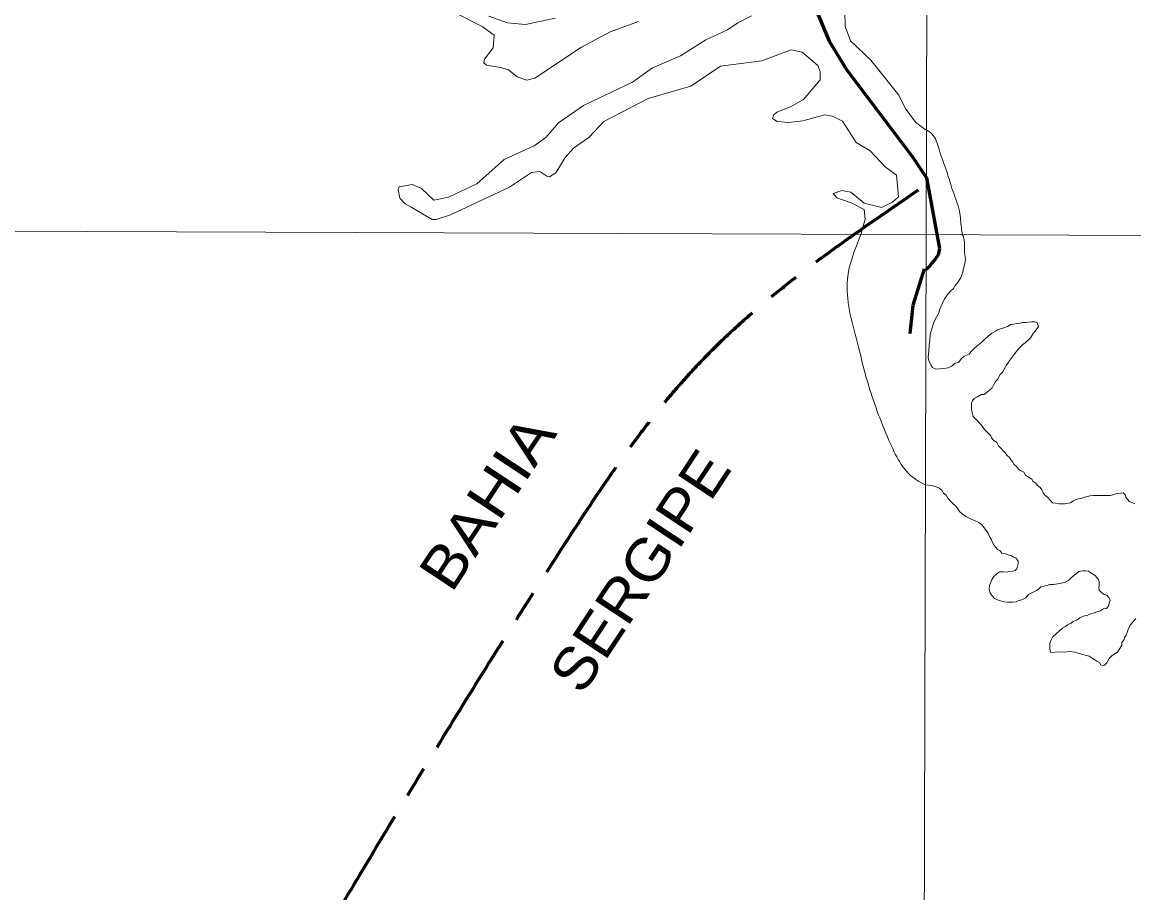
# Model space of a CAD drawing. Extents: x -1643653 to 4543381, y 1624270 to 13878484.
# Drawn here: x 601111 to 611751, y 8943403 to 8951740 of the extents above; entities that cross this region are included whole.
import ezdxf
from ezdxf.enums import TextEntityAlignment as Align

# ---------------------------------------------------------------- set-up
doc = ezdxf.new("R2010")
doc.units = 0
doc.header["$LTSCALE"] = 200
doc.linetypes.add('LONG_DASH_SHORT_DASH', pattern=[9.9, 6, -1.2, 1.5, -1.2])
for name, color, linetype, lineweight in [('1', 7, 'Continuous', 13), ('23', 7, 'Continuous', 13), ('25', 7, 'Continuous', 13), ('60', 7, 'Continuous', 13), ('7', 7, 'LONG_DASH_SHORT_DASH', 60)]:
    doc.layers.add(name, color=color, linetype=linetype, lineweight=lineweight)
doc.layers.add('42', color=7, linetype='Continuous')

msp = doc.modelspace()

# ---------------------------------------------------------------- linework, layer by layer
at = {"layer": '1'}
msp.add_line((565315.3, 8949866.8), (791497.7, 8949052.2), dxfattribs=at)
msp.add_lwpolyline([(609971.9, 9023551.8), (609764.7, 8949706.7), (609734.2, 8939404.4)], dxfattribs=at)
at = {"layer": '23'}
for points in [[(609755.4, 8950712.2), (609661.1, 8950783.5), (609561, 8950917.9), (609502.2, 8951042.1), (609232.8, 8951376.9), (609037.8, 8951563.3), (608987.2, 8951699.7), (608983.5, 8951846.5)], [(609755.4, 8950712.2), (609661.1, 8950783.5), (609561, 8950917.9), (609502.2, 8951042.1), (609232.8, 8951376.9), (609037.8, 8951563.3), (608987.2, 8951699.7), (608983.5, 8951846.5)], [(609792.6, 8948650.3), (609799.1, 8948692.7), (609802.3, 8948751.2), (609825.2, 8948822.9), (609838.2, 8948868.4), (609861, 8948914), (609887.1, 8948962.8), (609893.6, 8948992.1), (609916.4, 8949044.2), (609935.9, 8949083.3), (609968.5, 8949132.1), (610001.1, 8949167.9), (610023.9, 8949190.7), (610040.2, 8949220), (610069.5, 8949252.6), (610095.5, 8949294.9), (610115.1, 8949347), (610121.6, 8949382.8), (610134.6, 8949428.4), (610141.1, 8949473.9), (610130.7, 8949532.9), (610130.9, 8949558), (610131.1, 8949578), (610131.3, 8949608.1), (610129, 8949638.1), (610124.3, 8949673.2), (610117, 8949693.3), (610108.9, 8949704.2)], [(609792.6, 8948650.3), (609799.1, 8948692.7), (609802.3, 8948751.2), (609825.2, 8948822.9), (609838.2, 8948868.4), (609861, 8948914), (609887.1, 8948962.8), (609893.6, 8948992.1), (609916.4, 8949044.2), (609935.9, 8949083.3), (609968.5, 8949132.1), (610001.1, 8949167.9), (610023.9, 8949190.7), (610040.2, 8949220), (610069.5, 8949252.6), (610095.5, 8949294.9), (610115.1, 8949347), (610121.6, 8949382.8), (610134.6, 8949428.4), (610141.1, 8949473.9), (610130.7, 8949532.9), (610130.9, 8949558), (610131.1, 8949578), (610131.3, 8949608.1), (610129, 8949638.1), (610124.3, 8949673.2), (610117, 8949693.3), (610108.9, 8949704.2)], [(610788.6, 8947343.2), (610773.7, 8947363.3), (610741.4, 8947383.6), (610714, 8947401.3), (610696.7, 8947431.4), (610669.3, 8947444.1), (610646.9, 8947459.3), (610629.6, 8947486.9), (610607.2, 8947504.6), (610592.4, 8947527.2), (610577.6, 8947547.4), (610560.2, 8947570), (610537.9, 8947590.2), (610515.6, 8947617.9), (610498.2, 8947638), (610480.8, 8947658.2), (610456, 8947683.4), (610438.8, 8947716), (610408.9, 8947736.2), (610389.1, 8947758.9), (610381.7, 8947779), (610361.9, 8947799.2), (610342, 8947821.8), (610319.7, 8947842), (610299.9, 8947872.2), (610282.5, 8947892.3), (610265.2, 8947912.5), (610232.9, 8947945.2), (610213.1, 8947965.4), (610205.8, 8947990.5), (610198.6, 8948030.6), (610196.3, 8948068.1), (610196.5, 8948090.7), (610206.7, 8948113.1), (610224.4, 8948135.5), (610254.5, 8948152.9), (610292.2, 8948175.1), (610319.7, 8948175), (610342.4, 8948194.8), (610367.5, 8948214.7), (610395.2, 8948239.6), (610407.9, 8948264.5), (610425.7, 8948299.4), (610450.9, 8948321.8), (610458.6, 8948344.3), (610471.2, 8948366.7), (610493.9, 8948389.1), (610533.4, 8948456.2), (610564.5, 8948504.9), (610611, 8948567), (610646.5, 8948613.2), (610686.8, 8948650.5), (610711.9, 8948670.4), (610749.7, 8948705.2), (610767.4, 8948727.6), (610787.7, 8948760), (610807.8, 8948782.4), (610838.2, 8948827.3), (610825.9, 8948859.9), (610803.5, 8948870.1), (610771, 8948870.3), (610741, 8948868), (610720.9, 8948865.6), (610683.4, 8948863.3), (610663.3, 8948858.5), (610630.8, 8948853.7), (610600.7, 8948848.9), (610573.2, 8948846.6), (610540.6, 8948826.7), (610505.4, 8948814.5), (610475.3, 8948802.1), (610447.8, 8948794.8), (610427.6, 8948779.9), (610392.5, 8948762.6), (610372.4, 8948747.7), (610330.1, 8948712.2), (610330.1, 8948712.2), (610297.5, 8948676.4), (610297.5, 8948676.4), (610248.6, 8948637.3), (610219.3, 8948611.3), (610219.3, 8948611.3), (610193.3, 8948585.2), (610173.7, 8948562.4), (610128.1, 8948542.9), (610102.1, 8948520.1), (610076, 8948484.3), (610033.6, 8948471.3), (610010.8, 8948448.5), (609975, 8948429), (609932.7, 8948422.5), (609892.2, 8948420.5), (609854.5, 8948416), (609854.5, 8948416), (609825.2, 8948432.2), (609808.9, 8948458.3), (609808.9, 8948458.3), (609789.3, 8948500.6), (609782.8, 8948533.1), (609789.3, 8948588.5), (609792.6, 8948650.3)], [(610788.6, 8947343.2), (610773.7, 8947363.3), (610741.4, 8947383.6), (610714, 8947401.3), (610696.7, 8947431.4), (610669.3, 8947444.1), (610646.9, 8947459.3), (610629.6, 8947486.9), (610607.2, 8947504.6), (610592.4, 8947527.2), (610577.6, 8947547.4), (610560.2, 8947570), (610537.9, 8947590.2), (610515.6, 8947617.9), (610498.2, 8947638), (610480.8, 8947658.2), (610456, 8947683.4), (610438.8, 8947716), (610408.9, 8947736.2), (610389.1, 8947758.9), (610381.7, 8947779), (610361.9, 8947799.2), (610342, 8947821.8), (610319.7, 8947842), (610299.9, 8947872.2), (610282.5, 8947892.3), (610265.2, 8947912.5), (610232.9, 8947945.2), (610213.1, 8947965.4), (610205.8, 8947990.5), (610198.6, 8948030.6), (610196.3, 8948068.1), (610196.5, 8948090.7), (610206.7, 8948113.1), (610224.4, 8948135.5), (610254.5, 8948152.9), (610292.2, 8948175.1), (610319.7, 8948175), (610342.4, 8948194.8), (610367.5, 8948214.7), (610395.2, 8948239.6), (610407.9, 8948264.5), (610425.7, 8948299.4), (610450.9, 8948321.8), (610458.6, 8948344.3), (610471.2, 8948366.7), (610493.9, 8948389.1), (610533.4, 8948456.2), (610564.5, 8948504.9), (610611, 8948567), (610646.5, 8948613.2), (610686.8, 8948650.5), (610711.9, 8948670.4), (610749.7, 8948705.2), (610767.4, 8948727.6), (610787.7, 8948760), (610807.8, 8948782.4), (610838.2, 8948827.3), (610825.9, 8948859.9), (610803.5, 8948870.1), (610771, 8948870.3), (610741, 8948868), (610720.9, 8948865.6), (610683.4, 8948863.3), (610663.3, 8948858.5), (610630.8, 8948853.7), (610600.7, 8948848.9), (610573.2, 8948846.6), (610540.6, 8948826.7), (610505.4, 8948814.5), (610475.3, 8948802.1), (610447.8, 8948794.8), (610427.6, 8948779.9), (610392.5, 8948762.6), (610372.4, 8948747.7), (610330.1, 8948712.2), (610330.1, 8948712.2), (610297.5, 8948676.4), (610297.5, 8948676.4), (610248.6, 8948637.3), (610219.3, 8948611.3), (610219.3, 8948611.3), (610193.3, 8948585.2), (610173.7, 8948562.4), (610128.1, 8948542.9), (610102.1, 8948520.1), (610076, 8948484.3), (610033.6, 8948471.3), (610010.8, 8948448.5), (609975, 8948429), (609932.7, 8948422.5), (609892.2, 8948420.5), (609854.5, 8948416), (609854.5, 8948416), (609825.2, 8948432.2), (609808.9, 8948458.3), (609808.9, 8948458.3), (609789.3, 8948500.6), (609782.8, 8948533.1), (609789.3, 8948588.5), (609792.6, 8948650.3)], [(611759.9, 8947129), (611732.5, 8947141.7), (611705, 8947149.4), (611695.2, 8947169.4), (611675.3, 8947189.6), (611670.5, 8947209.7), (611650.6, 8947232.3), (611630.6, 8947230), (611598.1, 8947227.7), (611578, 8947222.8), (611558, 8947217.9), (611527.9, 8947208.1), (611507.9, 8947208.2), (611475.4, 8947208.5), (611445.4, 8947208.7), (611422.8, 8947208.8), (611400.3, 8947209), (611380.3, 8947209.1), (611357.8, 8947206.7), (611330.3, 8947204.4), (611310.2, 8947199.5), (611280.2, 8947192.2), (611252.6, 8947182.4), (611222.5, 8947175.1), (611199.9, 8947167.7), (611167.3, 8947152.9), (611144.7, 8947138.1), (611109.6, 8947130.8), (611089.6, 8947128.4), (611057.1, 8947128.6), (611037.1, 8947128.8), (611002.1, 8947134), (610972.1, 8947136.7), (610954.8, 8947159.3), (610925, 8947192.1), (610900.1, 8947212.3), (610882.8, 8947232.4), (610870.5, 8947262.5), (610855.7, 8947285.2), (610825.8, 8947305.4), (610813.5, 8947325.5), (610788.6, 8947343.2)], [(611759.9, 8947129), (611732.5, 8947141.7), (611705, 8947149.4), (611695.2, 8947169.4), (611675.3, 8947189.6), (611670.5, 8947209.7), (611650.6, 8947232.3), (611630.6, 8947230), (611598.1, 8947227.7), (611578, 8947222.8), (611558, 8947217.9), (611527.9, 8947208.1), (611507.9, 8947208.2), (611475.4, 8947208.5), (611445.4, 8947208.7), (611422.8, 8947208.8), (611400.3, 8947209), (611380.3, 8947209.1), (611357.8, 8947206.7), (611330.3, 8947204.4), (611310.2, 8947199.5), (611280.2, 8947192.2), (611252.6, 8947182.4), (611222.5, 8947175.1), (611199.9, 8947167.7), (611167.3, 8947152.9), (611144.7, 8947138.1), (611109.6, 8947130.8), (611089.6, 8947128.4), (611057.1, 8947128.6), (611037.1, 8947128.8), (611002.1, 8947134), (610972.1, 8947136.7), (610954.8, 8947159.3), (610925, 8947192.1), (610900.1, 8947212.3), (610882.8, 8947232.4), (610870.5, 8947262.5), (610855.7, 8947285.2), (610825.8, 8947305.4), (610813.5, 8947325.5), (610788.6, 8947343.2)]]:
    msp.add_lwpolyline(points, dxfattribs=at)
msp.add_spline([(610108.9, 8949704.2), (610092.8, 8949844.8), (610081.3, 8949930.9), (610018.2, 8950125.9), (609960.9, 8950309.5), (609886.3, 8950521.8), (609817.5, 8950670.9), (609755.4, 8950712.2)], degree=3, dxfattribs=at)
msp.add_spline([(610108.9, 8949704.2), (610092.8, 8949844.8), (610081.3, 8949930.9), (610018.2, 8950125.9), (609960.9, 8950309.5), (609886.3, 8950521.8), (609817.5, 8950670.9), (609755.4, 8950712.2)], degree=3, dxfattribs=at)
at = {"layer": '25'}
for points in [[(609755.4, 8950712.2), (609661.1, 8950783.5), (609561, 8950917.9), (609502.2, 8951042.1), (609232.8, 8951376.9), (609037.8, 8951563.3), (608987.2, 8951699.7), (608983.5, 8951846.5)], [(608090.2, 8951799.8), (607960.9, 8951735.6), (607862.5, 8951666.2), (607653, 8951570.5), (607410.8, 8951418.3), (607144.4, 8951302.6), (606950.8, 8951166.6), (606482.1, 8950942.3), (606242.9, 8950775.2), (606123, 8950635.5), (606012.1, 8950556.7), (605725, 8950424.5), (605463.8, 8950193.5), (605190.6, 8950065.5), (605051.5, 8950037.1), (604931.9, 8950147.3), (604842.4, 8950186), (604720.3, 8950162.6), (604710.1, 8950138.4)], [(605267.2, 8951822), (605514.5, 8951699.4), (605627.5, 8951614.5), (605620, 8951495.8), (605536.3, 8951386.5), (605528.7, 8951351.7), (605555.2, 8951329.8), (605690.4, 8951305.3), (605763.9, 8951283), (605848.8, 8951216.1), (605942.1, 8951185.6), (606018, 8951204.4), (606463.2, 8951500.4), (606738.6, 8951647.1), (607011.1, 8951745.5)], [(606213.2, 8951778.7), (605929, 8951719.6), (605757, 8951735), (605578.7, 8951796.6)], [(604710.1, 8950138.4), (604726.6, 8950056.6), (604775, 8950000.1), (604833.2, 8949967.4), (605034.8, 8949852), (605074.3, 8949852.1), (605210.6, 8949895.6), (605776.5, 8950159.4), (605984.7, 8950300.3), (606066, 8950310.7), (606133.6, 8950266.2), (606157.8, 8950260.8), (606219.7, 8950297.6), (606309.2, 8950444.5), (606386.8, 8950535.4), (606539, 8950640.6), (606679, 8950789), (607103.1, 8951009.8), (607511.4, 8951127.6), (607793.4, 8951318.1), (608189.8, 8951370), (608470.1, 8951476.1), (608576.2, 8951452.3), (608726.2, 8951326.4), (608749.8, 8951266.5), (608747.2, 8951186.9), (608590.8, 8950999.1), (608464.4, 8950928.1), (608333.9, 8950879.5), (608305.4, 8950852.7), (608293.4, 8950819), (608336.8, 8950788.8), (608450, 8950780.2), (608584.4, 8950796.9), (608792.8, 8950853.3), (608865.7, 8950839.8)], [(608865.7, 8950839.8), (608961.3, 8950792.2), (609092.6, 8950589), (609228.6, 8950508.5), (609370.6, 8950354.8), (609479, 8950274.1), (609498.7, 8950068.9), (609441.2, 8950017.2), (609336.6, 8949965), (609169.4, 8950008.4), (609042.6, 8950111.6), (608957.7, 8950128.6), (608874.2, 8950101.3), (608908.7, 8950059.5), (609044.9, 8950008.9), (609169.7, 8949947.6), (609179.8, 8949852.8), (609137, 8949702.7)], [(609792.6, 8948650.3), (609799.1, 8948692.7), (609802.3, 8948751.2), (609825.2, 8948822.9), (609838.2, 8948868.4), (609861, 8948914), (609887.1, 8948962.8), (609893.6, 8948992.1), (609916.4, 8949044.2), (609935.9, 8949083.3), (609968.5, 8949132.1), (610001.1, 8949167.9), (610023.9, 8949190.7), (610040.2, 8949220), (610069.5, 8949252.6), (610095.5, 8949294.9), (610115.1, 8949347), (610121.6, 8949382.8), (610134.6, 8949428.4), (610141.1, 8949473.9), (610130.7, 8949532.9), (610130.9, 8949558), (610131.1, 8949578), (610131.3, 8949608.1), (610129, 8949638.1), (610124.3, 8949673.2), (610117, 8949693.3), (610108.9, 8949704.2)], [(610788.6, 8947343.2), (610773.7, 8947363.3), (610741.4, 8947383.6), (610714, 8947401.3), (610696.7, 8947431.4), (610669.3, 8947444.1), (610646.9, 8947459.3), (610629.6, 8947486.9), (610607.2, 8947504.6), (610592.4, 8947527.2), (610577.6, 8947547.4), (610560.2, 8947570), (610537.9, 8947590.2), (610515.6, 8947617.9), (610498.2, 8947638), (610480.8, 8947658.2), (610456, 8947683.4), (610438.8, 8947716), (610408.9, 8947736.2), (610389.1, 8947758.9), (610381.7, 8947779), (610361.9, 8947799.2), (610342, 8947821.8), (610319.7, 8947842), (610299.9, 8947872.2), (610282.5, 8947892.3), (610265.2, 8947912.5), (610232.9, 8947945.2), (610213.1, 8947965.4), (610205.8, 8947990.5), (610198.6, 8948030.6), (610196.3, 8948068.1), (610196.5, 8948090.7), (610206.7, 8948113.1), (610224.4, 8948135.5), (610254.5, 8948152.9), (610292.2, 8948175.1), (610319.7, 8948175), (610342.4, 8948194.8), (610367.5, 8948214.7), (610395.2, 8948239.6), (610407.9, 8948264.5), (610425.7, 8948299.4), (610450.9, 8948321.8), (610458.6, 8948344.3), (610471.2, 8948366.7), (610493.9, 8948389.1), (610533.4, 8948456.2), (610564.5, 8948504.9), (610611, 8948567), (610646.5, 8948613.2), (610686.8, 8948650.5), (610711.9, 8948670.4), (610749.7, 8948705.2), (610767.4, 8948727.6), (610787.7, 8948760), (610807.8, 8948782.4), (610838.2, 8948827.3), (610825.9, 8948859.9), (610803.5, 8948870.1), (610771, 8948870.3), (610741, 8948868), (610720.9, 8948865.6), (610683.4, 8948863.3), (610663.3, 8948858.5), (610630.8, 8948853.7), (610600.7, 8948848.9), (610573.2, 8948846.6), (610540.6, 8948826.7), (610505.4, 8948814.5), (610475.3, 8948802.1), (610447.8, 8948794.8), (610427.6, 8948779.9), (610392.5, 8948762.6), (610372.4, 8948747.7), (610330.1, 8948712.2), (610330.1, 8948712.2), (610297.5, 8948676.4), (610297.5, 8948676.4), (610248.6, 8948637.3), (610219.3, 8948611.3), (610219.3, 8948611.3), (610193.3, 8948585.2), (610173.7, 8948562.4), (610128.1, 8948542.9), (610102.1, 8948520.1), (610076, 8948484.3), (610033.6, 8948471.3), (610010.8, 8948448.5), (609975, 8948429), (609932.7, 8948422.5), (609892.2, 8948420.5), (609854.5, 8948416), (609854.5, 8948416), (609825.2, 8948432.2), (609808.9, 8948458.3), (609808.9, 8948458.3), (609789.3, 8948500.6), (609782.8, 8948533.1), (609789.3, 8948588.5), (609792.6, 8948650.3)], [(609757.5, 8947308.3), (609815.9, 8947301.8), (609850.4, 8947294.2), (609884.9, 8947280.7), (609915.6, 8947253.9), (609930.9, 8947229), (609953.9, 8947209.9), (609969.3, 8947183), (609969.3, 8947183), (609998, 8947148.6), (609998, 8947148.6), (610019.1, 8947129.4), (610043.1, 8947109), (610060.4, 8947088.9), (610082.7, 8947053.7), (610107.5, 8947031), (610141.8, 8947004.9), (610141.8, 8947004.9), (610194.6, 8946980.4), (610227.1, 8946967.6), (610266.9, 8946949.8), (610299.2, 8946922.1), (610314.1, 8946902), (610331.5, 8946881.8), (610356.2, 8946846.6), (610368.5, 8946816.5), (610388.2, 8946783.8), (610395.6, 8946763.7), (610412.8, 8946728.6), (610445.1, 8946690.8), (610470, 8946680.6), (610487.3, 8946655.5), (610522.2, 8946647.7), (610554.7, 8946637.5), (610577.2, 8946632.3), (610599.6, 8946617.2), (610622, 8946612), (610644.3, 8946579.3), (610644.1, 8946556.8), (610638.9, 8946529.3), (610631.2, 8946504.3), (610614, 8946490.7), (610590.3, 8946484), (610556.5, 8946480.6), (610530.9, 8946474.9), (610500.9, 8946475.1), (610465.9, 8946475.4), (610443.3, 8946460.5), (610410.6, 8946433.2), (610390.3, 8946398.2), (610381.7, 8946376.9), (610369.3, 8946345.4), (610365.9, 8946308.2), (610374.9, 8946274.4), (610391.8, 8946250.7), (610418.9, 8946220.3), (610453.9, 8946205.1), (610476.3, 8946197.4), (610513.8, 8946189.6), (610543.8, 8946186.9), (610588.8, 8946186.6), (610626.3, 8946188.9), (610646.4, 8946201.3), (610679, 8946208.6), (610716.7, 8946228.3), (610744.4, 8946260.7), (610782.1, 8946278), (610819.7, 8946297.8), (610842.4, 8946315.1), (610862.5, 8946332.5), (610882.6, 8946337.4), (610902.6, 8946342.3), (610925.1, 8946347.1), (610945.2, 8946354.5), (610982.7, 8946356.8), (611020.3, 8946361.5), (611057.9, 8946368.8), (611095.5, 8946378.6), (611128.1, 8946395.9), (611150.8, 8946418.2), (611170.9, 8946435.6), (611206.2, 8946465.4), (611226.3, 8946480.3), (611263.9, 8946487.6), (611288.9, 8946487.4), (611316.3, 8946482), (611350.2, 8946462), (611380.9, 8946440.5), (611411.6, 8946402.2), (611411.6, 8946402.2), (611418.1, 8946381.4), (611417.9, 8946346.4), (611417.7, 8946326.4), (611420, 8946301.3), (611439.9, 8946281.2), (611462.2, 8946263.5), (611492.2, 8946253.3), (611513, 8946231.7), (611524.3, 8946205.5), (611516.6, 8946178), (611508.9, 8946148)], [(611759.9, 8947129), (611732.5, 8947141.7), (611705, 8947149.4), (611695.2, 8947169.4), (611675.3, 8947189.6), (611670.5, 8947209.7), (611650.6, 8947232.3), (611630.6, 8947230), (611598.1, 8947227.7), (611578, 8947222.8), (611558, 8947217.9), (611527.9, 8947208.1), (611507.9, 8947208.2), (611475.4, 8947208.5), (611445.4, 8947208.7), (611422.8, 8947208.8), (611400.3, 8947209), (611380.3, 8947209.1), (611357.8, 8947206.7), (611330.3, 8947204.4), (611310.2, 8947199.5), (611280.2, 8947192.2), (611252.6, 8947182.4), (611222.5, 8947175.1), (611199.9, 8947167.7), (611167.3, 8947152.9), (611144.7, 8947138.1), (611109.6, 8947130.8), (611089.6, 8947128.4), (611057.1, 8947128.6), (611037.1, 8947128.8), (611002.1, 8947134), (610972.1, 8947136.7), (610954.8, 8947159.3), (610925, 8947192.1), (610900.1, 8947212.3), (610882.8, 8947232.4), (610870.5, 8947262.5), (610855.7, 8947285.2), (610825.8, 8947305.4), (610813.5, 8947325.5), (610788.6, 8947343.2)], [(611508.9, 8946148), (611488.7, 8946125.6), (611461.2, 8946123.3), (611431, 8946103.4), (611398.4, 8946093.7), (611370.8, 8946083.8), (611340.8, 8946074), (611310.6, 8946061.7), (611265.6, 8946052), (611232.9, 8946037.2), (611210.3, 8946017.3), (611170.1, 8946000), (611150, 8945985.1), (611117.3, 8945967.8), (611097.2, 8945952.9), (611069.6, 8945935.6), (611039.4, 8945910.8), (611011.4, 8945885.7), (610972.4, 8945850.4), (610955.6, 8945820.6), (610948.2, 8945789), (610948.2, 8945789), (610948.2, 8945740.7), (610953.8, 8945703.5)], [(610953.8, 8945703.5), (610994.7, 8945707.2), (611046.8, 8945709.1), (611091.4, 8945707.2), (611139.8, 8945714.6), (611186.3, 8945707.2), (611231, 8945694.2), (611262.6, 8945684.9), (611284.9, 8945679.3), (611322.2, 8945668.2), (611322.2, 8945668.2), (611353.8, 8945651.4), (611378, 8945634.7), (611398.4, 8945619.8), (611422.6, 8945606.8), (611433.8, 8945586.3), (611452.4, 8945578.9), (611471, 8945584), (611491.2, 8945606.4), (611516.5, 8945646.3), (611536.7, 8945668.7), (611556.8, 8945686.1), (611594.5, 8945705.9), (611617.3, 8945743.3), (611635.1, 8945775.7), (611637.7, 8945795.7), (611658, 8945828.2), (611660.6, 8945848.2), (611678.3, 8945870.6), (611691.1, 8945905.5), (611701.3, 8945935.5), (611719.1, 8945967.9), (611749.3, 8946005.3), (611769.5, 8946025.2)]]:
    msp.add_lwpolyline(points, dxfattribs=at)
for points in [[(610108.9, 8949704.2), (610092.8, 8949844.8), (610081.3, 8949930.9), (610018.2, 8950125.9), (609960.9, 8950309.5), (609886.3, 8950521.8), (609817.5, 8950670.9), (609755.4, 8950712.2)], [(609137, 8949702.7), (609010, 8949279.3), (609102.4, 8948678.5), (609204.1, 8948290.3), (609407.4, 8947735.7), (609657, 8947365.9), (609757.5, 8947308.3)]]:
    msp.add_spline(points, degree=3, dxfattribs=at)
at = {"layer": '60', "lineweight": 25}
msp.add_spline([(814781, 9009175.5), (814787.2, 9009173.4), (814796.9, 9009173.4), (814799.4, 9009172.4), (814805.1, 9009174.5), (814805.6, 9009176.5), (814811.7, 9009179.5), (814811.7, 9009179.5), (814801.5, 9009181), (814790.7, 9009181.5), (814784.1, 9009183.1), (814777.4, 9009185.1), (814778.4, 9009175.5)], degree=3, dxfattribs=at)
at = {"layer": '7'}
for points in [[(608709, 8951855.3), (608834.6, 8951559), (609001.1, 8951288.7), (609632.1, 8950450.2), (609766.1, 8950251.3)], [(609766.1, 8950251.3), (609892.1, 8949571.8), (609876.7, 8949511.8), (609848.8, 8949469.3), (609818.6, 8949432), (609785.7, 8949389.6), (609763.6, 8949371.8)], [(609608.9, 8948758.3), (609638.2, 8949029.6), (609745.9, 8949377.2)]]:
    msp.add_lwpolyline(points, dxfattribs=at)
msp.add_spline([(609688.1, 8950131.7), (607584.3, 8948466.4), (606301.7, 8946741.8), (602418.3, 8940294.4)], degree=3, dxfattribs=at)

# ---------------------------------------------------------------- texts
at = {"layer": '42'}
for s, width, p in [('BAHIA', 1.15, (605729.2, 8947032.4)), ('SERGIPE', 1.1, (607190.8, 8946373.9))]:
    msp.add_text(s, height=400, rotation=56.48, dxfattribs=dict(at, width=width)).set_placement(p, align=Align.CENTER)

doc.saveas('drawing.dxf')
